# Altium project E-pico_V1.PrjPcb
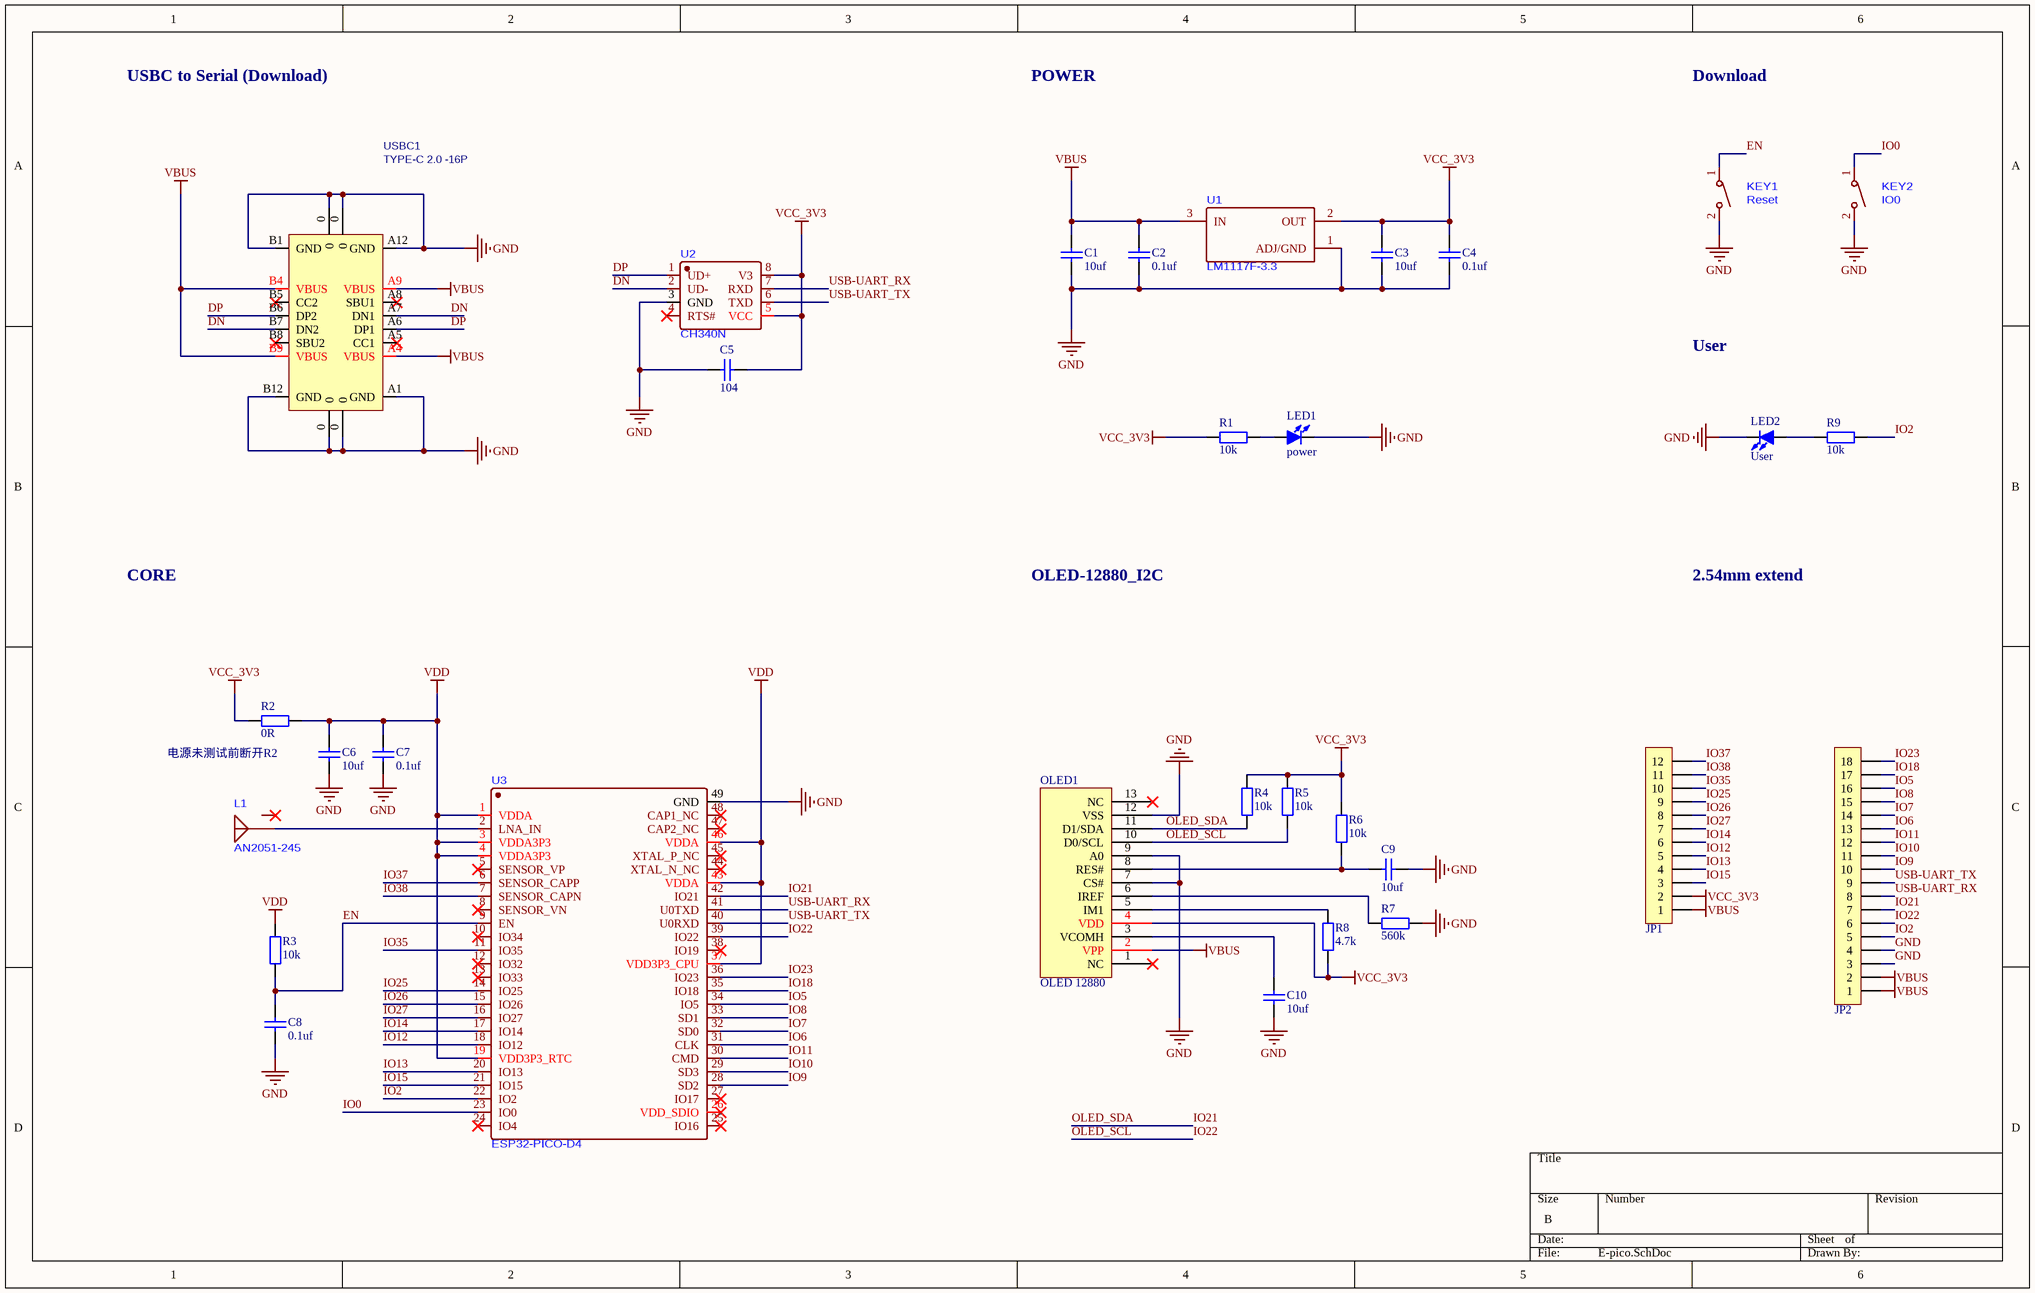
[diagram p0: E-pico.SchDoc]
1 sheet, 31 parts. Net scope: global (net labels, ports and power ports of the same name join across sheets).
Board file: E-pico.PcbDoc

## Sheet E-pico.SchDoc
size B; SheetNumber: 1; SheetTotal: 1

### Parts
C1  10uf  [C0603_M]
C2  0.1uf  [C0603_M]
C3  10uf  [C0603_M]
C4  0.1uf  [C0603_M]
C5  104  [C0603_M]
C6  10uf  [C0603_M]
C7  0.1uf  [C0603_M]
C8  0.1uf  [C0603_M]
C9  10uf  [C0603_M]
C10  10uf  [C0603_M]
JP1  HDR-1X12  [HDR2.54-LI-12P]  (value not drawn)
JP2  HDR-1X18  [HDR2.54-LI-18P]  (value not drawn)
KEY1  Reset  [SW-SMD_ST-1186S]
KEY2  IO0  [SW-SMD_ST-1186S]
L1  AN2051-245  [ANT2051]
LED1  power  [LED0603_Y]
LED2  User  [LED0603_Y]
OLED1  OLED 12880  [0.78'OLED-12880-13pin-short]
R1  10k  [R0603_M]
R2  0R  [R0603_M]
R3  10k  [R0603_M]
R4  10k  [R0603_M]
R5  10k  [R0603_M]
R6  10k  [R0603_M]
R7  560k  [R0603_M]
R8  4.7k  [R0603_M]
R9  10k  [R0603_M]
U1  LM1117F-3.3  [SOT89-150P410X160-3N]
U2  CH340N  [SOP-8_L5.0-W4.0-P1.27-LS6.0-BL]
U3  ESP32-PICO-D4  [QFN-48_L7.0-W7.0-P0.50-BL-EP5.4]
USBC1  TYPE-C 2.0 -16P  [USB-C-SMD_16P]

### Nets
GND: C1.2 C2.2 C3.2 C4.2 C5.1 C6.1 C7.1 C8.1 C9.1 C10.1 JP2.3 JP2.4 KEY1.2 KEY2.2 LED1.2(K) LED2.2(K) OLED1.7(CS#) OLED1.9(A0) OLED1.12(VSS) R7.1 U1.1(ADJ/GND) U2.3(GND) U3.49(GND) USBC1.0 USBC1.A1(GND) USBC1.A12(GND) USBC1.B1(GND) USBC1.B12(GND)
VBUS: C1.1 C2.1 JP1.1 JP2.1 JP2.2 OLED1.2(VPP) U1.3(IN) USBC1.A4(VBUS) USBC1.A9(VBUS) USBC1.B4(VBUS) USBC1.B9(VBUS)
VCC_3V3: C3.1 C4.1 C5.2 JP1.2 OLED1.4(VDD) R1.1 R2.1 R4.1 R5.1 R6.1 R8.1 U1.2(OUT) U2.5(VCC) U2.8(V3)
VDD: C6.2 C7.2 R2.2 R3.1 U3.1(VDDA) U3.3(VDDA3P3) U3.4(VDDA3P3) U3.19(VDD3P3_RTC) U3.37(VDD3P3_CPU) U3.43(VDDA) U3.46(VDDA)
DN: U2.2(UD-) USBC1.A7(DN1) USBC1.B7(DN2)
DP: U2.1(UD+) USBC1.A6(DP1) USBC1.B6(DP2)
EN: C8.2 KEY1.1 R3.2 U3.9(EN)
IO0: KEY2.1 U3.23(IO0)
IO2: JP2.5 R9.1 U3.22(IO2)
IO5: JP2.16 U3.34(IO5)
IO6: JP2.13 U3.31(CLK)
IO7: JP2.14 U3.32(SD0)
IO8: JP2.15 U3.33(SD1)
IO9: JP2.10 U3.28(SD2)
IO10: JP2.11 U3.29(SD3)
IO11: JP2.12 U3.30(CMD)
IO12: JP1.5 U3.18(IO12)
IO13: JP1.4 U3.20(IO13)
IO14: JP1.6 U3.17(IO14)
IO15: JP1.3 U3.21(IO15)
IO18: JP2.17 U3.35(IO18)
IO21: JP2.7 OLED1.11(D1/SDA) R4.2 U3.42(IO21)  [also labelled OLED_SDA]
IO22: JP2.6 OLED1.10(D0/SCL) R5.2 U3.39(IO22)  [also labelled OLED_SCL]
IO23: JP2.18 U3.36(IO23)
IO25: JP1.9 U3.14(IO25)
IO26: JP1.8 U3.15(IO26)
IO27: JP1.7 U3.16(IO27)
IO35: JP1.10 U3.11(IO35)
IO37: JP1.12 U3.6(SENSOR_CAPP)
IO38: JP1.11 U3.7(SENSOR_CAPN)
USB-UART_RX: JP2.8 U2.7(RXD) U3.41(U0TXD)
USB-UART_TX: JP2.9 U2.6(TXD) U3.40(U0RXD)
NetC9_2: C9.2 OLED1.8(RES#) R6.2
NetC10_2: C10.2 OLED1.3(VCOMH)
NetL1_1: L1.1(ANT) U3.2(LNA_IN)
NetLED1_1: LED1.1(A) R1.2
NetLED2_1: LED2.1(A) R9.2
NetOLED1_5: OLED1.5(IM1) R8.2
NetOLED1_6: OLED1.6(IREF) R7.2

Not connected (* = marked no-connect by the designer): L1 2*; OLED1 1(NC)* 13(NC)*; U2 4(RTS#)*; U3 5(SENSOR_VP)* 8(SENSOR_VN)* 10(IO34)* 12(IO32)* 13(IO33)* 24(IO4)* 25(IO16)* 26(VDD_SDIO)* 27(IO17)* 38(IO19)* 44(XTAL_N_NC)* 45(XTAL_P_NC)* 47(CAP2_NC)* 48(CAP1_NC)*; USBC1 A5(CC1)* A8(SBU1)* B5(CC2)* B8(SBU2)*

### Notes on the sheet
- USBC to Serial (Download)
- POWER
- Download
- User
- CORE
- OLED-12880_I2C
- 2.54mm extend
- 电源未测试前断开R2

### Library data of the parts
C1-C10 = C: 贴片电容/MLCC电容; BOM名称: 无极性贴片电容; 联系卖家，免费查找封装: 唯一出售店铺网址https://shop463601444.taobao.com
JP1 = Header 12: 12P接插件; 联系卖家，免费查找封装: 唯一出售店铺网址https://shop463601444.taobao.com; 封装库来自淘宝卖家ID:黄晶宝石: 其他店铺购入均为盗版假冒封装库，请立即申请退款，本店现金奖励20~200元
JP2 = Header 18: 18P接插件; 联系卖家，免费查找封装: 唯一出售店铺网址https://shop463601444.taobao.com; 封装库来自淘宝卖家ID:黄晶宝石: 其他店铺购入均为盗版假冒封装库，请立即申请退款，本店现金奖励20~200元
KEY1 KEY2 = 侧按小龟ST-1186S: C589199
LED1 LED2 = LED-SMD: 贴片LED; 封装库来自淘宝卖家ID：黄晶宝石: 其他店铺购入均为盗版封装库，请立即申请退款，本店现金奖励20~200元
OLED1 = 0.78寸12880oled
R1-R9 = R: 贴片电阻; 联系卖家，免费查找封装: 唯一出售店铺网址https://shop463601444.taobao.com
USBC1 = USB2.0_Type-C_16Pin: USB2.0_Type-C_16Pin母座; 联系卖家 免费技术支持: 封装库来自淘宝卖家ID：黄晶宝石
